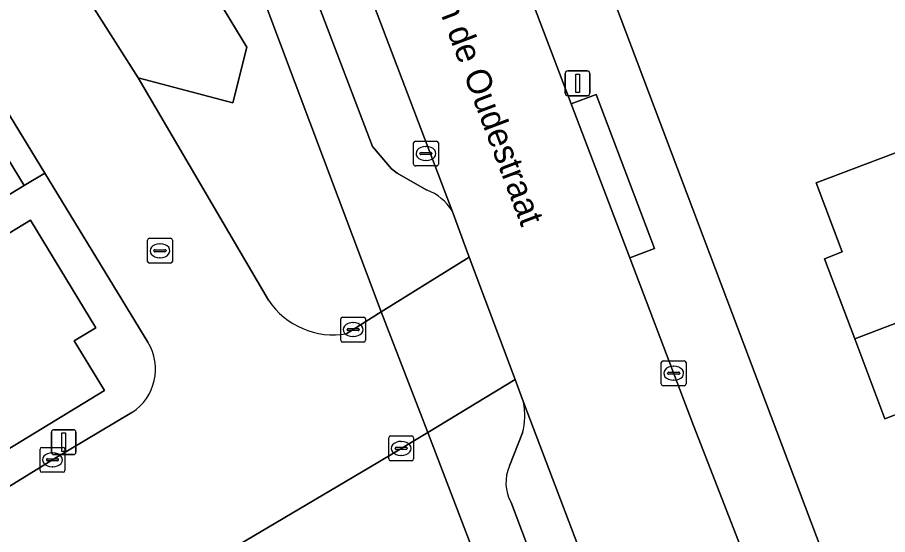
# Model space of a CAD drawing. Extents: x 159960 to 160866, y 382700 to 383354.
# Drawn here: x 160353.88 to 160388.88, y 382972.64 to 382993.44 of the extents above; entities that cross this region are included whole.
import ezdxf

# ---------------------------------------------------------------- set-up
doc = ezdxf.new("R2010")
doc.units = 0
for name, color, linetype in [('IMGEO_Erf', 7, 'Continuous'), ('IMGEO_Groenvoorziening', 7, 'Continuous'), ('IMGEO_Kolk', 7, 'Continuous'), ('IMGEO_Lichtmast', 7, 'Continuous'), ('IMGEO_Openbare_ruimte_label', 7, 'Continuous'), ('IMGEO_Pand', 7, 'Continuous'), ('IMGEO_Parkeervlak_open', 7, 'Continuous'), ('IMGEO_Rijbaan_lokaal_open', 7, 'Continuous'), ('IMGEO_Rioolput', 7, 'Continuous'), ('IMGEO_Voetpad_open', 7, 'Continuous')]:
    doc.layers.add(name, color=color, linetype=linetype)

msp = doc.modelspace()

# ---------------------------------------------------------------- linework, layer by layer
at = {"layer": 'IMGEO_Erf'}
msp.add_lwpolyline([(160359.868, 383041.772), (160375.649, 383000), (160389.164, 382964.227)], dxfattribs=at)
for points in [[(160338.283, 382990.248), (160336.511, 382993.16), (160332.352, 383000), (160325.073, 383011.971), (160323.309, 383014.872), (160317.351, 383024.674), (160327.335, 383030.788), (160346.052, 383000), (160354.153, 382986.675), (160354.977, 382987.18), (160328.108, 383031.263), (160328.241, 383031.36), (160327.687, 383032.3), (160315.507, 383024.71), (160316.015, 383023.874), (160321.983, 383014.084), (160323.762, 383011.165), (160330.567, 383000), (160335.219, 382992.368), (160336.996, 382989.452), (160342.867, 382979.821), (160344.157, 382980.593)], [(160390.681, 382988.554), (160396.528, 382990.766), (160398.782, 382984.807), (160396.556, 382983.965), (160397.772, 382980.758), (160398.53, 382981.045), (160399.642, 382978.111), (160398.886, 382977.82), (160395.307, 382976.443), (160390.63, 382974.674), (160389.528, 382977.587), (160388.772, 382977.301), (160387.555, 382980.518), (160386.339, 382983.734), (160387.055, 382984.005), (160386.004, 382986.785)]]:
    msp.add_lwpolyline(points, close=True, dxfattribs=at)
at = {"layer": 'IMGEO_Groenvoorziening'}
for points in [[(160330.218, 383037.075), (160336.761, 383035.598), (160350.986, 383012.188), (160358.396, 383000), (160363.112, 382992.243), (160362.536, 382990.002), (160358.735, 382991.005), (160363.982, 382982.064)], [(160367.124, 382980.721), (160368.513, 382981.603), (160361.585, 383000), (160361.047, 383001.415), (160350.986, 383027.855)], [(160370.391, 382976.746), (160368.931, 382975.876), (160368.007, 382975.329), (160359.645, 382970.375)], [(160381.544, 382935.915), (160385.083, 382938.344), (160370.391, 382976.746)]]:
    msp.add_lwpolyline(points, dxfattribs=at)
msp.add_lwpolyline([(160350.081, 382973.991), (160357.379, 382978.431), (160356.163, 382980.43), (160357.034, 382980.96), (160354.404, 382985.283), (160345.212, 382979.69), (160349.058, 382973.368)], close=True, dxfattribs=at)
msp.add_arc((160366.574, 382983.78), 3.108, 213.5141, 280.1988, dxfattribs=at)
at = {"layer": 'IMGEO_Kolk'}
for p, q in [((160369.885, 382988.463), (160370.737, 382988.463)), ((160369.81, 382987.537), (160369.81, 382988.389)), ((160370.298, 382988.243), (160370.323, 382988.243)), ((160370.811, 382988.389), (160370.811, 382987.537)), ((160370.069, 382987.957), (160370.069, 382987.969)), ((160370.507, 382987.92), (160370.109, 382987.92)), ((160370.112, 382988.006), (160370.51, 382988.006)), ((160370.553, 382987.969), (160370.553, 382987.957)), ((160370.737, 382987.463), (160369.885, 382987.463)), ((160370.321, 382987.683), (160370.296, 382987.683)), ((160366.881, 382980.458), (160366.881, 382981.31)), ((160366.956, 382981.384), (160367.808, 382981.384)), ((160367.369, 382981.164), (160367.394, 382981.164)), ((160367.882, 382981.31), (160367.882, 382980.458)), ((160367.14, 382980.878), (160367.14, 382980.89)), ((160367.578, 382980.841), (160367.18, 382980.841)), ((160367.183, 382980.927), (160367.581, 382980.927)), ((160367.624, 382980.89), (160367.624, 382980.878)), ((160367.808, 382980.384), (160366.956, 382980.384)), ((160367.392, 382980.604), (160367.367, 382980.604)), ((160379.773, 382978.702), (160379.773, 382979.554)), ((160379.848, 382979.628), (160380.7, 382979.628)), ((160380.261, 382979.408), (160380.286, 382979.408)), ((160380.774, 382979.554), (160380.774, 382978.702)), ((160380.032, 382979.122), (160380.032, 382979.134)), ((160380.47, 382979.085), (160380.072, 382979.085)), ((160380.075, 382979.171), (160380.473, 382979.171)), ((160380.516, 382979.134), (160380.516, 382979.122)), ((160380.7, 382978.628), (160379.848, 382978.628)), ((160380.284, 382978.848), (160380.259, 382978.848)), ((160368.814, 382975.68), (160368.814, 382976.532)), ((160368.889, 382976.606), (160369.741, 382976.606)), ((160369.815, 382976.532), (160369.815, 382975.68)), ((160369.302, 382976.386), (160369.327, 382976.386)), ((160354.79, 382975.22), (160354.79, 382976.072)), ((160354.865, 382976.146), (160355.717, 382976.146)), ((160355.278, 382975.926), (160355.303, 382975.926)), ((160355.791, 382976.072), (160355.791, 382975.22)), ((160369.073, 382976.1), (160369.073, 382976.112)), ((160369.511, 382976.063), (160369.113, 382976.063)), ((160369.116, 382976.149), (160369.514, 382976.149)), ((160369.557, 382976.112), (160369.557, 382976.1)), ((160355.049, 382975.64), (160355.049, 382975.652)), ((160355.487, 382975.603), (160355.089, 382975.603)), ((160355.092, 382975.689), (160355.49, 382975.689)), ((160355.533, 382975.652), (160355.533, 382975.64)), ((160369.741, 382975.606), (160368.889, 382975.606)), ((160369.325, 382975.826), (160369.3, 382975.826)), ((160355.717, 382975.146), (160354.865, 382975.146)), ((160355.301, 382975.366), (160355.276, 382975.366))]:
    msp.add_line(p, q, dxfattribs=at)
for points in [[(160369.885, 382988.463), (160370.737, 382988.463)], [(160369.81, 382987.537), (160369.81, 382988.389)], [(160370.811, 382988.389), (160370.811, 382987.537)], [(160370.737, 382987.463), (160369.885, 382987.463)], [(160366.881, 382980.458), (160366.881, 382981.31)], [(160366.956, 382981.384), (160367.808, 382981.384)], [(160367.882, 382981.31), (160367.882, 382980.458)], [(160367.808, 382980.384), (160366.956, 382980.384)], [(160379.773, 382978.702), (160379.773, 382979.554)], [(160379.848, 382979.628), (160380.7, 382979.628)], [(160380.774, 382979.554), (160380.774, 382978.702)], [(160380.7, 382978.628), (160379.848, 382978.628)], [(160368.814, 382975.68), (160368.814, 382976.532)], [(160368.889, 382976.606), (160369.741, 382976.606)], [(160369.815, 382976.532), (160369.815, 382975.68)], [(160354.79, 382975.22), (160354.79, 382976.072)], [(160354.865, 382976.146), (160355.717, 382976.146)], [(160355.791, 382976.072), (160355.791, 382975.22)], [(160369.741, 382975.606), (160368.889, 382975.606)], [(160355.717, 382975.146), (160354.865, 382975.146)]]:
    msp.add_lwpolyline(points, dxfattribs=at)
for centre, radius, start, end in [((160369.887, 382988.387), 0.0765, 91.552, 178.448), ((160369.887, 382988.387), 0.0765, 91.552, 178.448), ((160370.735, 382988.387), 0.0765, 1.552, 88.448), ((160370.735, 382988.387), 0.0765, 1.552, 88.448), ((160370.109, 382987.966), 0.0403, 85.8775, 175.7526), ((160370.106, 382987.956), 0.0366, 178.938, 274.7102), ((160370.51, 382987.963), 0.043, 264.8664, 352.4533), ((160370.514, 382987.968), 0.0386, 1.7309, 96.639), ((160369.887, 382987.539), 0.0765, 181.552, 268.448), ((160369.887, 382987.539), 0.0765, 181.552, 268.448), ((160370.735, 382987.539), 0.0765, 271.552, 358.448), ((160370.735, 382987.539), 0.0765, 271.552, 358.448), ((160366.958, 382981.308), 0.0765, 91.552, 178.448), ((160366.958, 382981.308), 0.0765, 91.552, 178.448), ((160367.806, 382981.308), 0.0765, 1.552, 88.448), ((160367.806, 382981.308), 0.0765, 1.552, 88.448), ((160367.18, 382980.887), 0.0403, 85.8775, 175.7526), ((160367.177, 382980.877), 0.0366, 178.938, 274.7102), ((160367.581, 382980.884), 0.043, 264.8664, 352.4533), ((160367.585, 382980.889), 0.0386, 1.7309, 96.639), ((160366.958, 382980.46), 0.0765, 181.552, 268.448), ((160366.958, 382980.46), 0.0765, 181.552, 268.448), ((160367.806, 382980.46), 0.0765, 271.552, 358.448), ((160367.806, 382980.46), 0.0765, 271.552, 358.448), ((160379.85, 382979.552), 0.0765, 91.552, 178.448), ((160379.85, 382979.552), 0.0765, 91.552, 178.448), ((160380.698, 382979.552), 0.0765, 1.552, 88.448), ((160380.698, 382979.552), 0.0765, 1.552, 88.448), ((160380.072, 382979.131), 0.0403, 85.8775, 175.7526), ((160380.069, 382979.121), 0.0366, 178.938, 274.7102), ((160380.473, 382979.128), 0.043, 264.8664, 352.4533), ((160380.477, 382979.133), 0.0386, 1.7309, 96.639), ((160379.85, 382978.704), 0.0765, 181.552, 268.448), ((160379.85, 382978.704), 0.0765, 181.552, 268.448), ((160380.698, 382978.704), 0.0765, 271.552, 358.448), ((160380.698, 382978.704), 0.0765, 271.552, 358.448), ((160368.891, 382976.53), 0.0765, 91.552, 178.448), ((160368.891, 382976.53), 0.0765, 91.552, 178.448), ((160369.739, 382976.53), 0.0765, 1.552, 88.448), ((160369.739, 382976.53), 0.0765, 1.552, 88.448), ((160354.867, 382976.07), 0.0765, 91.552, 178.448), ((160354.867, 382976.07), 0.0765, 91.552, 178.448), ((160355.715, 382976.07), 0.0765, 1.552, 88.448), ((160355.715, 382976.07), 0.0765, 1.552, 88.448), ((160369.113, 382976.109), 0.0403, 85.8775, 175.7526), ((160369.11, 382976.099), 0.0366, 178.938, 274.7102), ((160369.514, 382976.106), 0.043, 264.8664, 352.4533), ((160369.518, 382976.111), 0.0386, 1.7309, 96.639), ((160355.089, 382975.649), 0.0403, 85.8775, 175.7526), ((160355.086, 382975.639), 0.0366, 178.938, 274.7102), ((160355.49, 382975.646), 0.043, 264.8664, 352.4533), ((160355.494, 382975.651), 0.0386, 1.7309, 96.639), ((160368.891, 382975.682), 0.0765, 181.552, 268.448), ((160368.891, 382975.682), 0.0765, 181.552, 268.448), ((160369.739, 382975.682), 0.0765, 271.552, 358.448), ((160369.739, 382975.682), 0.0765, 271.552, 358.448), ((160354.867, 382975.222), 0.0765, 181.552, 268.448), ((160354.867, 382975.222), 0.0765, 181.552, 268.448), ((160355.715, 382975.222), 0.0765, 271.552, 358.448), ((160355.715, 382975.222), 0.0765, 271.552, 358.448)]:
    msp.add_arc(centre, radius, start, end, dxfattribs=at)
for centre, major_axis, ratio, start_param, end_param in [((160370.297, 382987.963), (-0.387, 0.002), 0.722429, 4.712389, 7.853982), ((160370.322, 382987.963), (-0.39, 0.002), 0.717154, 1.570796, 4.712389), ((160367.368, 382980.884), (-0.387, 0.002), 0.722429, 4.712389, 7.853982), ((160367.393, 382980.884), (-0.39, 0.002), 0.717154, 1.570796, 4.712389), ((160380.26, 382979.128), (-0.387, 0.002), 0.722429, 4.712389, 7.853982), ((160380.285, 382979.128), (-0.39, 0.002), 0.717154, 1.570796, 4.712389), ((160369.301, 382976.106), (-0.387, 0.002), 0.722429, 4.712389, 7.853982), ((160369.326, 382976.106), (-0.39, 0.002), 0.717154, 1.570796, 4.712389), ((160355.277, 382975.646), (-0.387, 0.002), 0.722429, 4.712389, 7.853982), ((160355.302, 382975.646), (-0.39, 0.002), 0.717154, 1.570796, 4.712389)]:
    msp.add_ellipse(centre, major_axis=major_axis, ratio=ratio, start_param=start_param, end_param=end_param, dxfattribs=at)
at = {"layer": 'IMGEO_Lichtmast'}
for p, q in [((160376.012, 382991.287), (160376.802, 382991.287)), ((160376.802, 382991.287), (160376.012, 382991.287)), ((160375.912, 382990.387), (160375.912, 382991.187)), ((160375.912, 382991.187), (160375.912, 382990.387)), ((160376.902, 382991.187), (160376.902, 382990.387)), ((160376.902, 382990.387), (160376.902, 382991.187)), ((160376.802, 382990.287), (160376.012, 382990.287)), ((160376.012, 382990.287), (160376.802, 382990.287)), ((160355.244, 382975.958), (160355.244, 382976.758)), ((160355.244, 382976.758), (160355.244, 382975.958)), ((160355.344, 382976.858), (160356.134, 382976.858)), ((160356.134, 382976.858), (160355.344, 382976.858)), ((160356.234, 382976.758), (160356.234, 382975.958)), ((160356.234, 382975.958), (160356.234, 382976.758)), ((160356.134, 382975.858), (160355.344, 382975.858)), ((160355.344, 382975.858), (160356.134, 382975.858))]:
    msp.add_line(p, q, dxfattribs=at)
for points in [[(160376.332, 382991.162), (160376.482, 382991.162), (160376.482, 382990.412), (160376.332, 382990.412), (160376.332, 382991.162)], [(160355.664, 382976.733), (160355.814, 382976.733), (160355.814, 382975.983), (160355.664, 382975.983), (160355.664, 382976.733)]]:
    msp.add_lwpolyline(points, dxfattribs=at)
for centre, start, end in [((160376.012, 382991.187), 90, 180), ((160376.012, 382991.187), 90, 180), ((160376.802, 382991.187), 0, 90), ((160376.802, 382991.187), 360, 90), ((160376.012, 382990.387), 180, 270), ((160376.012, 382990.387), 180, 270), ((160376.802, 382990.387), 270, 0), ((160376.802, 382990.387), 270, 0), ((160355.344, 382976.758), 90, 180), ((160355.344, 382976.758), 90, 180), ((160356.134, 382976.758), 0, 90), ((160356.134, 382976.758), 360, 90), ((160355.344, 382975.958), 180, 270), ((160355.344, 382975.958), 180, 270), ((160356.134, 382975.958), 270, 0), ((160356.134, 382975.958), 270, 0)]:
    msp.add_arc(centre, 0.1, start, end, dxfattribs=at)
at = {"layer": 'IMGEO_Pand'}
for points in [[(160354.153, 382986.675), (160346.052, 383000), (160327.335, 383030.788), (160317.351, 383024.674), (160323.309, 383014.872), (160325.073, 383011.971), (160332.352, 383000), (160336.511, 382993.16), (160338.283, 382990.248), (160344.157, 382980.593), (160344.524, 382980.816)], [(160396.556, 382983.965), (160398.782, 382984.807), (160396.528, 382990.766), (160390.681, 382988.554), (160386.004, 382986.785), (160387.055, 382984.005), (160386.339, 382983.734), (160387.555, 382980.518), (160396.127, 382983.789)], [(160397.772, 382980.758), (160396.556, 382983.965), (160396.127, 382983.789), (160387.555, 382980.518), (160388.772, 382977.301), (160389.528, 382977.587), (160390.63, 382974.674), (160395.307, 382976.443), (160398.886, 382977.82), (160399.642, 382978.111), (160398.53, 382981.045)]]:
    msp.add_lwpolyline(points, close=True, dxfattribs=at)
at = {"layer": 'IMGEO_Parkeervlak_open'}
for points in [[(160328.956, 383037.843), (160353.016, 383000), (160358.735, 382991.005), (160362.536, 382990.002), (160363.112, 382992.243), (160358.396, 383000), (160350.986, 383012.188), (160336.761, 383035.598), (160330.218, 383037.075)], [(160350.986, 383033.342), (160363.686, 383000), (160368.162, 382988.249), (160368.93, 382987.351), (160369.147, 382987.178), (160370.352, 382986.491)], [(160371.361, 382985.658), (160365.907, 383000), (160364.36, 383004.067), (160355.596, 383027.043)], [(160387.933, 382941.868), (160382.246, 382956.868), (160374.234, 382977.967)], [(160374.194, 382976.732), (160373.671, 382975.399)], [(160373.732, 382973.926), (160385.042, 382943.913)]]:
    msp.add_lwpolyline(points, dxfattribs=at)
for centre, radius, start, end in [((160369.687, 382984.658), 1.95, 30.8589, 70.057), ((160371.564, 382977.435), 2.722, 345.0256, 11.2642), ((160375.187, 382974.724), 1.66, 156.0053, 208.7375)]:
    msp.add_arc(centre, radius, start, end, dxfattribs=at)
at = {"layer": 'IMGEO_Rijbaan_lokaal_open'}
for points in [[(160363.982, 382982.064), (160358.735, 382991.005), (160353.016, 383000), (160328.956, 383037.843), (160328.163, 383039.213), (160324.759, 383037.085), (160327.687, 383032.3), (160328.241, 383031.36), (160328.108, 383031.263), (160354.977, 382987.18), (160359.126, 382980.375)], [(160351.648, 383037.333), (160355.596, 383027.043), (160364.36, 383004.067), (160365.907, 383000), (160371.361, 382985.658), (160372.054, 382983.802), (160373.893, 382978.879), (160374.234, 382977.967), (160382.246, 382956.868)], [(160383.064, 382971.894), (160381.072, 382977.03), (160378.506, 382983.775), (160376.152, 382989.964), (160372.662, 382999.136), (160369.104, 383008.582)], [(160359.645, 382970.375), (160368.007, 382975.329), (160368.931, 382975.876), (160370.391, 382976.746), (160368.513, 382981.603), (160367.124, 382980.721)], [(160358.481, 382977.554), (160355.325, 382975.667), (160350.766, 382972.869), (160377.609, 382928.902), (160381.033, 382931.054), (160385.877, 382933.973), (160386.604, 382934.424), (160385.083, 382938.344), (160381.544, 382935.915)]]:
    msp.add_lwpolyline(points, dxfattribs=at)
msp.add_lwpolyline([(160373.893, 382978.879), (160372.054, 382983.802), (160368.513, 382981.603), (160370.391, 382976.746)], close=True, dxfattribs=at)
for centre, radius, start, end in [((160366.574, 382983.78), 3.108, 213.5141, 280.1988), ((160357.377, 382979.291), 2.058, 302.4508, 31.7915)]:
    msp.add_arc(centre, radius, start, end, dxfattribs=at)
at = {"layer": 'IMGEO_Rioolput'}
for p, q in [((160359.112, 382983.628), (160359.112, 382984.48)), ((160359.187, 382984.554), (160360.039, 382984.554)), ((160359.6, 382984.334), (160359.625, 382984.334)), ((160360.113, 382984.48), (160360.113, 382983.628)), ((160359.371, 382984.048), (160359.371, 382984.06)), ((160359.809, 382984.011), (160359.411, 382984.011)), ((160359.414, 382984.097), (160359.812, 382984.097)), ((160359.855, 382984.06), (160359.855, 382984.048)), ((160360.039, 382983.554), (160359.187, 382983.554)), ((160359.623, 382983.774), (160359.598, 382983.774))]:
    msp.add_line(p, q, dxfattribs=at)
for points in [[(160359.112, 382983.628), (160359.112, 382984.48)], [(160359.187, 382984.554), (160360.039, 382984.554)], [(160360.113, 382984.48), (160360.113, 382983.628)], [(160360.039, 382983.554), (160359.187, 382983.554)]]:
    msp.add_lwpolyline(points, dxfattribs=at)
for centre, radius, start, end in [((160359.189, 382984.478), 0.0765, 91.552, 178.448), ((160359.189, 382984.478), 0.0765, 91.552, 178.448), ((160360.037, 382984.478), 0.0765, 1.552, 88.448), ((160360.037, 382984.478), 0.0765, 1.552, 88.448), ((160359.411, 382984.057), 0.0403, 85.8775, 175.7526), ((160359.408, 382984.047), 0.0366, 178.938, 274.7102), ((160359.812, 382984.054), 0.043, 264.8664, 352.4533), ((160359.816, 382984.059), 0.0386, 1.7309, 96.639), ((160359.189, 382983.63), 0.0765, 181.552, 268.448), ((160359.189, 382983.63), 0.0765, 181.552, 268.448), ((160360.037, 382983.63), 0.0765, 271.552, 358.448), ((160360.037, 382983.63), 0.0765, 271.552, 358.448)]:
    msp.add_arc(centre, radius, start, end, dxfattribs=at)
for centre, major_axis, ratio, start_param, end_param in [((160359.599, 382984.054), (-0.387, 0.002), 0.722429, 4.712389, 7.853982), ((160359.624, 382984.054), (-0.39, 0.002), 0.717154, 1.570796, 4.712389)]:
    msp.add_ellipse(centre, major_axis=major_axis, ratio=ratio, start_param=start_param, end_param=end_param, dxfattribs=at)
at = {"layer": 'IMGEO_Voetpad_open'}
for points in [[(160346.241, 383045.476), (160349.347, 383037.342), (160348.346, 383034.778), (160348.704, 383033.84), (160350.986, 383027.855), (160361.047, 383001.415), (160361.585, 383000), (160368.513, 382981.603), (160372.054, 382983.802), (160371.361, 382985.658)], [(160357.364, 383039.449), (160358.612, 383036.208), (160359.899, 383032.829), (160360.868, 383033.194), (160361.857, 383030.651), (160363.156, 383027.265), (160362.16, 383026.893), (160365.936, 383016.959), (160366.867, 383014.503), (160367.849, 383014.857), (160370.091, 383008.973), (160369.104, 383008.582), (160372.662, 382999.136), (160376.152, 382989.964), (160377.158, 382990.335), (160379.504, 382984.142), (160378.506, 382983.775), (160381.072, 382977.03), (160383.064, 382971.894)], [(160370.352, 382986.491), (160369.147, 382987.178), (160368.93, 382987.351), (160368.162, 382988.249), (160363.686, 383000), (160350.986, 383033.342)], [(160398.331, 382939.97), (160396.349, 382945.207), (160389.569, 382963.154), (160389.164, 382964.227), (160375.649, 383000)], [(160359.126, 382980.375), (160354.977, 382987.18), (160354.153, 382986.675), (160344.524, 382980.816), (160345.212, 382979.69), (160354.404, 382985.283), (160357.034, 382980.96), (160356.163, 382980.43), (160357.379, 382978.431), (160350.081, 382973.991), (160350.766, 382972.869), (160355.325, 382975.667), (160358.481, 382977.554)], [(160374.234, 382977.967), (160373.893, 382978.879), (160370.391, 382976.746), (160385.083, 382938.344), (160388.41, 382940.623), (160387.933, 382941.868)], [(160373.671, 382975.399), (160374.194, 382976.732)], [(160385.042, 382943.913), (160373.732, 382973.926)]]:
    msp.add_lwpolyline(points, dxfattribs=at)
msp.add_lwpolyline([(160376.152, 382989.964), (160378.506, 382983.775), (160379.504, 382984.142), (160377.158, 382990.335)], close=True, dxfattribs=at)
for centre, radius, start, end in [((160369.687, 382984.658), 1.95, 30.8589, 70.057), ((160357.377, 382979.291), 2.058, 302.4508, 31.7915), ((160371.564, 382977.435), 2.722, 345.0256, 11.2642), ((160375.187, 382974.724), 1.66, 156.0053, 208.7375)]:
    msp.add_arc(centre, radius, start, end, dxfattribs=at)

# ---------------------------------------------------------------- texts
at = {"layer": 'IMGEO_Openbare_ruimte_label'}
msp.add_text('Jan de Oudestraat', height=1, rotation=290.7907, dxfattribs=at).set_placement((160370.252, 382995.265))

doc.saveas('drawing.dxf')
